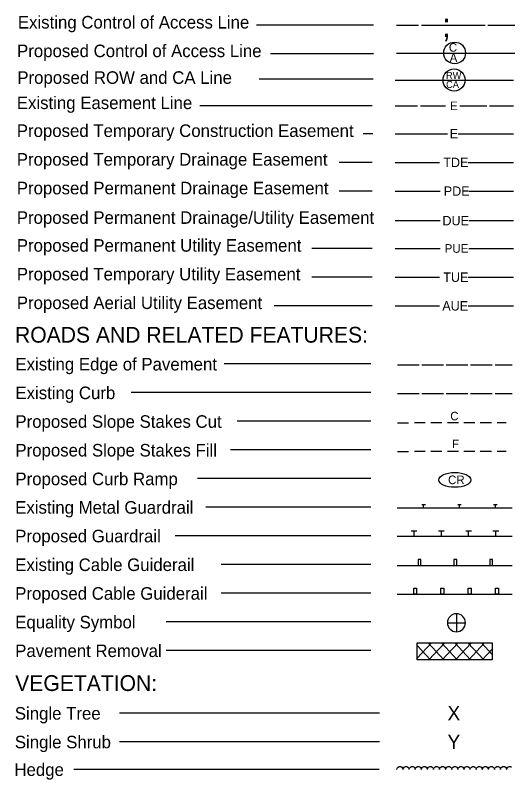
# Model space of a CAD drawing. Extents: x 2058324 to 2059808, y 675202 to 676238.
# Drawn here: x 2058730 to 2059078, y 675202 to 675735 of the extents above; entities that cross this region are included whole.
import ezdxf

# ---------------------------------------------------------------- set-up
doc = ezdxf.new("R2010")
doc.units = 0
for name, color, linetype in [('Prop Easement Permanent Drainage Utility', 7, 'Continuous'), ('Prop WCC CELL', 7, 'Continuous'), ('Sheet Symbology CELL', 7, 'Continuous')]:
    doc.layers.add(name, color=color, linetype=linetype)

msp = doc.modelspace()

# ---------------------------------------------------------------- linework, layer by layer
at = {"layer": 'Prop Easement Permanent Drainage Utility'}
for p, q in [((2058994.73, 675591.85), (2059026.03, 675591.85)), ((2059046.03, 675591.85), (2059077.23, 675591.85))]:
    msp.add_line(p, q, dxfattribs=at)
at = {"layer": 'Prop WCC CELL'}
msp.add_ellipse((2059036.23, 675411.03), major_axis=(11.21, 0), ratio=0.462467, dxfattribs=at)
at = {"layer": 'Sheet Symbology CELL'}
for p, q in [((2058979.44, 675728.07), (2058898.12, 675728.07)), ((2058995.47, 675728.07), (2059010.93, 675728.07)), ((2059012.93, 675728.07), (2059057.34, 675728.07)), ((2059059.34, 675728.07), (2059077.97, 675728.07)), ((2058979.44, 675708.26), (2058907.79, 675708.26)), ((2058995.47, 675708.64), (2059077.97, 675708.64)), ((2058979.33, 675690.5), (2058899.97, 675690.5)), ((2058994.74, 675689.73), (2059077.24, 675689.73)), ((2058978.7, 675671.88), (2058858.42, 675671.88)), ((2058994.73, 675671.88), (2059010.24, 675671.88)), ((2059012.24, 675671.88), (2059029.74, 675671.88)), ((2059039.74, 675671.88), (2059058.49, 675671.88)), ((2059060.49, 675671.88), (2059077.23, 675671.88)), ((2058979.08, 675652.43), (2058972.41, 675652.43)), ((2058994.73, 675652.43), (2058997.34, 675652.43)), ((2058997.34, 675652.43), (2059031.09, 675652.43)), ((2059038.59, 675652.43), (2059072.34, 675652.43)), ((2059072.34, 675652.43), (2059077.23, 675652.43)), ((2058978.7, 675632.43), (2058955.55, 675632.43)), ((2058994.73, 675632.43), (2058998.08, 675632.43)), ((2058998.08, 675632.43), (2059025.58, 675632.43)), ((2059045.58, 675632.43), (2059073.08, 675632.43)), ((2059073.08, 675632.43), (2059077.23, 675632.43)), ((2058978.7, 675612.43), (2058955.55, 675612.43)), ((2058994.73, 675612.43), (2058998.53, 675612.43)), ((2058998.53, 675612.43), (2059026.03, 675612.43)), ((2059046.03, 675612.43), (2059073.53, 675612.43)), ((2059073.53, 675612.43), (2059077.23, 675612.43)), ((2058978.7, 675572.42), (2058936.56, 675572.42)), ((2058994.73, 675572.42), (2058998.57, 675572.42)), ((2058998.57, 675572.42), (2059026.07, 675572.42)), ((2059046.07, 675572.42), (2059073.57, 675572.42)), ((2059073.57, 675572.42), (2059077.23, 675572.42)), ((2058978.7, 675552.42), (2058936.56, 675552.42)), ((2058994.73, 675552.42), (2058998.08, 675552.42)), ((2058998.08, 675552.42), (2059025.58, 675552.42)), ((2059045.58, 675552.42), (2059073.08, 675552.42)), ((2059073.08, 675552.42), (2059077.23, 675552.42)), ((2058978.7, 675532.42), (2058910.24, 675532.42)), ((2058994.73, 675532.42), (2058998.08, 675532.42)), ((2058998.08, 675532.42), (2059025.58, 675532.42)), ((2059045.58, 675532.42), (2059073.08, 675532.42)), ((2059073.08, 675532.42), (2059077.23, 675532.42)), ((2058977.74, 675491.89), (2058875.39, 675491.89)), ((2058996.27, 675491.32), (2059011.27, 675491.32)), ((2059013.27, 675491.32), (2059028.27, 675491.32)), ((2059030.27, 675491.32), (2059045.27, 675491.32)), ((2059047.27, 675491.32), (2059062.27, 675491.32)), ((2059064.27, 675491.32), (2059076.27, 675491.32)), ((2058977.74, 675471.89), (2058810.59, 675471.89)), ((2058996.27, 675471.32), (2059011.27, 675471.32)), ((2059013.27, 675471.32), (2059028.27, 675471.32)), ((2059030.27, 675471.32), (2059045.27, 675471.32)), ((2059047.27, 675471.32), (2059062.27, 675471.32)), ((2059064.27, 675471.32), (2059076.27, 675471.32)), ((2058977.74, 675451.89), (2058884.55, 675451.89)), ((2058996.27, 675450.84), (2059003.87, 675450.84)), ((2059015.57, 675450.84), (2059008.02, 675450.84)), ((2059027.07, 675450.84), (2059019.47, 675450.84)), ((2059038.82, 675450.84), (2059031.02, 675450.84)), ((2059050.27, 675450.84), (2059042.52, 675450.84)), ((2059061.82, 675450.84), (2059053.97, 675450.84)), ((2059072.12, 675450.84), (2059065.72, 675450.84)), ((2058977.74, 675431.89), (2058880, 675431.89)), ((2058996.27, 675430.84), (2059003.87, 675430.84)), ((2059015.57, 675430.84), (2059008.02, 675430.84)), ((2059027.07, 675430.84), (2059019.47, 675430.84)), ((2059038.82, 675430.84), (2059031.02, 675430.84)), ((2059050.27, 675430.84), (2059042.52, 675430.84)), ((2059061.82, 675430.84), (2059053.97, 675430.84)), ((2059072.12, 675430.84), (2059065.72, 675430.84)), ((2058977.74, 675411.89), (2058856.81, 675411.89)), ((2059013.25, 675393.94), (2059015.75, 675393.94)), ((2059014.5, 675391.44), (2059014.5, 675393.94)), ((2059038.25, 675393.94), (2059040.75, 675393.94)), ((2059039.5, 675391.44), (2059039.5, 675393.94)), ((2059063.25, 675393.94), (2059065.75, 675393.94)), ((2059064.5, 675391.44), (2059064.5, 675393.94)), ((2058977.58, 675392.01), (2058862.74, 675392.01)), ((2058996.11, 675391.44), (2059076.11, 675391.44)), ((2058977.58, 675372.01), (2058841.34, 675372.01)), ((2059076.11, 675371.44), (2058996.11, 675371.44)), ((2059005.84, 675375.39), (2059009.84, 675375.39)), ((2059007.84, 675371.44), (2059007.84, 675375.39)), ((2059024.84, 675375.39), (2059028.84, 675375.39)), ((2059026.84, 675371.44), (2059026.84, 675375.39)), ((2059043.84, 675375.39), (2059047.84, 675375.39)), ((2059045.84, 675371.44), (2059045.84, 675375.39)), ((2059062.84, 675375.39), (2059066.84, 675375.39)), ((2059064.84, 675371.44), (2059064.84, 675375.39)), ((2058977.58, 675352.01), (2058873.28, 675352.01)), ((2058996.11, 675351.44), (2059076.11, 675351.44)), ((2058977.58, 675332.01), (2058873.28, 675332.01)), ((2058996.11, 675331.44), (2059076.11, 675331.44)), ((2059037.34, 675317.68), (2059037.34, 675311.43)), ((2058977.58, 675312.01), (2058834.96, 675312.01)), ((2059031.09, 675311.43), (2059037.34, 675311.43)), ((2059037.34, 675311.43), (2059037.34, 675305.18)), ((2059037.34, 675311.43), (2059043.59, 675311.43)), ((2059010.06, 675297.3), (2059062.16, 675297.3)), ((2059010.06, 675285.6), (2059010.06, 675297.3)), ((2059010.06, 675296.7), (2059010.61, 675297.3)), ((2059010.06, 675286.75), (2059019.91, 675297.3)), ((2059028.61, 675285.6), (2059017.61, 675297.3)), ((2059018.21, 675285.6), (2059029.21, 675297.3)), ((2059037.86, 675285.6), (2059026.91, 675297.3)), ((2059027.46, 675285.6), (2059038.51, 675297.3)), ((2059047.16, 675285.6), (2059036.16, 675297.3)), ((2059036.76, 675285.6), (2059047.76, 675297.3)), ((2059056.46, 675285.6), (2059045.41, 675297.3)), ((2059046.06, 675285.6), (2059057.01, 675297.3)), ((2059062.16, 675289.35), (2059054.71, 675297.3)), ((2059062.16, 675297.3), (2059062.16, 675285.6)), ((2058977.58, 675292.01), (2058834.96, 675292.01)), ((2059019.31, 675285.6), (2059010.06, 675295.5)), ((2059055.31, 675285.6), (2059062.16, 675292.9)), ((2059062.16, 675285.6), (2059010.06, 675285.6)), ((2058983.72, 675248.37), (2058802.59, 675248.37)), ((2058983.72, 675228.37), (2058802.59, 675228.37)), ((2058983.45, 675209.11), (2058770.76, 675209.11)), ((2058995.84, 675209.11), (2058996.14, 675210.06)), ((2058996.14, 675210.06), (2058996.74, 675210.71)), ((2058996.74, 675210.71), (2058997.54, 675211.16)), ((2058997.54, 675211.16), (2058998.49, 675211.16)), ((2058998.49, 675211.16), (2058999.29, 675210.66)), ((2058999.29, 675210.66), (2058999.84, 675210.01)), ((2058999.84, 675210.01), (2059000.04, 675209.16)), ((2059000.09, 675209.11), (2059000.39, 675210.06)), ((2059000.39, 675210.06), (2059000.99, 675210.71)), ((2059000.99, 675210.71), (2059001.79, 675211.16)), ((2059001.79, 675211.16), (2059002.74, 675211.16)), ((2059002.74, 675211.16), (2059003.54, 675210.66)), ((2059003.54, 675210.66), (2059004.09, 675210.01)), ((2059004.09, 675210.01), (2059004.29, 675209.16)), ((2059004.34, 675209.11), (2059004.64, 675210.06)), ((2059004.64, 675210.06), (2059005.24, 675210.71)), ((2059005.24, 675210.71), (2059006.04, 675211.16)), ((2059006.04, 675211.16), (2059006.99, 675211.16)), ((2059006.99, 675211.16), (2059007.79, 675210.66)), ((2059007.79, 675210.66), (2059008.34, 675210.01)), ((2059008.34, 675210.01), (2059008.54, 675209.16)), ((2059008.59, 675209.11), (2059008.89, 675210.06)), ((2059008.89, 675210.06), (2059009.49, 675210.71)), ((2059009.49, 675210.71), (2059010.29, 675211.16)), ((2059010.29, 675211.16), (2059011.24, 675211.16)), ((2059011.24, 675211.16), (2059012.04, 675210.66)), ((2059012.04, 675210.66), (2059012.59, 675210.01)), ((2059012.59, 675210.01), (2059012.79, 675209.16)), ((2059012.84, 675209.11), (2059013.14, 675210.06)), ((2059013.14, 675210.06), (2059013.74, 675210.71)), ((2059013.74, 675210.71), (2059014.54, 675211.16)), ((2059014.54, 675211.16), (2059015.49, 675211.16)), ((2059015.49, 675211.16), (2059016.29, 675210.66)), ((2059016.29, 675210.66), (2059016.84, 675210.01)), ((2059016.84, 675210.01), (2059017.04, 675209.16)), ((2059017.09, 675209.11), (2059017.39, 675210.06)), ((2059017.39, 675210.06), (2059017.99, 675210.71)), ((2059017.99, 675210.71), (2059018.79, 675211.16)), ((2059018.79, 675211.16), (2059019.74, 675211.16)), ((2059019.74, 675211.16), (2059020.54, 675210.66)), ((2059020.54, 675210.66), (2059021.09, 675210.01)), ((2059021.09, 675210.01), (2059021.29, 675209.16)), ((2059021.34, 675209.11), (2059021.64, 675210.06)), ((2059021.64, 675210.06), (2059022.24, 675210.71)), ((2059022.24, 675210.71), (2059023.04, 675211.16)), ((2059023.04, 675211.16), (2059023.99, 675211.16)), ((2059023.99, 675211.16), (2059024.79, 675210.66)), ((2059024.79, 675210.66), (2059025.34, 675210.01)), ((2059025.34, 675210.01), (2059025.54, 675209.16)), ((2059025.59, 675209.11), (2059025.89, 675210.06)), ((2059025.89, 675210.06), (2059026.49, 675210.71)), ((2059026.49, 675210.71), (2059027.29, 675211.16)), ((2059027.29, 675211.16), (2059028.24, 675211.16)), ((2059028.24, 675211.16), (2059029.04, 675210.66)), ((2059029.04, 675210.66), (2059029.59, 675210.01)), ((2059029.59, 675210.01), (2059029.79, 675209.16)), ((2059029.84, 675209.11), (2059030.14, 675210.06)), ((2059030.14, 675210.06), (2059030.74, 675210.71)), ((2059030.74, 675210.71), (2059031.54, 675211.16)), ((2059031.54, 675211.16), (2059032.49, 675211.16)), ((2059032.49, 675211.16), (2059033.29, 675210.66)), ((2059033.29, 675210.66), (2059033.84, 675210.01)), ((2059033.84, 675210.01), (2059034.04, 675209.16)), ((2059034.09, 675209.11), (2059034.39, 675210.06)), ((2059034.39, 675210.06), (2059034.99, 675210.71)), ((2059034.99, 675210.71), (2059035.79, 675211.16)), ((2059035.79, 675211.16), (2059036.74, 675211.16)), ((2059036.74, 675211.16), (2059037.54, 675210.66)), ((2059037.54, 675210.66), (2059038.09, 675210.01)), ((2059038.09, 675210.01), (2059038.29, 675209.16)), ((2059038.34, 675209.11), (2059038.64, 675210.06)), ((2059038.64, 675210.06), (2059039.24, 675210.71)), ((2059039.24, 675210.71), (2059040.04, 675211.16)), ((2059040.04, 675211.16), (2059040.99, 675211.16)), ((2059040.99, 675211.16), (2059041.79, 675210.66)), ((2059041.79, 675210.66), (2059042.34, 675210.01)), ((2059042.34, 675210.01), (2059042.54, 675209.16)), ((2059042.59, 675209.11), (2059042.89, 675210.06)), ((2059042.89, 675210.06), (2059043.49, 675210.71)), ((2059043.49, 675210.71), (2059044.29, 675211.16)), ((2059044.29, 675211.16), (2059045.24, 675211.16)), ((2059045.24, 675211.16), (2059046.04, 675210.66)), ((2059046.04, 675210.66), (2059046.59, 675210.01)), ((2059046.59, 675210.01), (2059046.79, 675209.16)), ((2059046.84, 675209.11), (2059047.14, 675210.06)), ((2059047.14, 675210.06), (2059047.74, 675210.71)), ((2059047.74, 675210.71), (2059048.54, 675211.16)), ((2059048.54, 675211.16), (2059049.49, 675211.16)), ((2059049.49, 675211.16), (2059050.29, 675210.66)), ((2059050.29, 675210.66), (2059050.84, 675210.01)), ((2059050.84, 675210.01), (2059051.04, 675209.16)), ((2059051.09, 675209.11), (2059051.39, 675210.06)), ((2059051.39, 675210.06), (2059051.99, 675210.71)), ((2059051.99, 675210.71), (2059052.79, 675211.16)), ((2059052.79, 675211.16), (2059053.74, 675211.16)), ((2059053.74, 675211.16), (2059054.54, 675210.66)), ((2059054.54, 675210.66), (2059055.09, 675210.01)), ((2059055.09, 675210.01), (2059055.29, 675209.16)), ((2059055.34, 675209.11), (2059055.64, 675210.06)), ((2059055.64, 675210.06), (2059056.24, 675210.71)), ((2059056.24, 675210.71), (2059057.04, 675211.16)), ((2059057.04, 675211.16), (2059057.99, 675211.16)), ((2059057.99, 675211.16), (2059058.79, 675210.66)), ((2059058.79, 675210.66), (2059059.34, 675210.01)), ((2059059.34, 675210.01), (2059059.54, 675209.16)), ((2059059.59, 675209.11), (2059059.89, 675210.06)), ((2059059.89, 675210.06), (2059060.49, 675210.71)), ((2059060.49, 675210.71), (2059061.29, 675211.16)), ((2059061.29, 675211.16), (2059062.24, 675211.16)), ((2059062.24, 675211.16), (2059063.04, 675210.66)), ((2059063.04, 675210.66), (2059063.59, 675210.01)), ((2059063.59, 675210.01), (2059063.79, 675209.16)), ((2059063.84, 675209.11), (2059064.14, 675210.06)), ((2059064.14, 675210.06), (2059064.74, 675210.71)), ((2059064.74, 675210.71), (2059065.54, 675211.16)), ((2059065.54, 675211.16), (2059066.49, 675211.16)), ((2059066.49, 675211.16), (2059067.29, 675210.66)), ((2059067.29, 675210.66), (2059067.84, 675210.01)), ((2059067.84, 675210.01), (2059068.04, 675209.16)), ((2059068.09, 675209.11), (2059068.39, 675210.06)), ((2059068.39, 675210.06), (2059068.99, 675210.71)), ((2059068.99, 675210.71), (2059069.79, 675211.16)), ((2059069.79, 675211.16), (2059070.74, 675211.16)), ((2059070.74, 675211.16), (2059071.54, 675210.66)), ((2059071.54, 675210.66), (2059072.09, 675210.01)), ((2059072.09, 675210.01), (2059072.29, 675209.16)), ((2059072.34, 675209.11), (2059072.64, 675210.06)), ((2059072.64, 675210.06), (2059073.24, 675210.71)), ((2059073.24, 675210.71), (2059074.04, 675211.16)), ((2059074.04, 675211.16), (2059074.99, 675211.16)), ((2059074.99, 675211.16), (2059075.79, 675210.66)), ((2059075.79, 675210.66), (2059075.84, 675210.61))]:
    msp.add_line(p, q, dxfattribs=at)
for points in [[(2059010.59, 675351.44), (2059012.59, 675351.44), (2059012.59, 675355.44), (2059010.59, 675355.44)], [(2059035.59, 675351.44), (2059037.59, 675351.44), (2059037.59, 675355.44), (2059035.59, 675355.44)], [(2059060.59, 675351.44), (2059062.59, 675351.44), (2059062.59, 675355.44), (2059060.59, 675355.44)], [(2059007.57, 675335.44), (2059009.57, 675335.44), (2059009.57, 675331.44), (2059007.57, 675331.44)], [(2059026.57, 675335.44), (2059028.57, 675335.44), (2059028.57, 675331.44), (2059026.57, 675331.44)], [(2059045.57, 675335.44), (2059047.57, 675335.44), (2059047.57, 675331.44), (2059045.57, 675331.44)], [(2059064.57, 675335.44), (2059066.57, 675335.44), (2059066.57, 675331.44), (2059064.57, 675331.44)]]:
    msp.add_lwpolyline(points, close=True, dxfattribs=at)
for centre, radius in [((2059036.11, 675708.74), 7.58), ((2059035.73, 675689.88), 7.72)]:
    msp.add_circle(centre, radius, dxfattribs=at)
for start, end in [(89.9944, 179.9989), (359.9944, 89.9989), (179.9944, 269.9989), (269.9944, 359.9989)]:
    msp.add_arc((2059037.34, 675311.42), 6.25, start, end, dxfattribs=at)

# ---------------------------------------------------------------- texts
at = {"layer": 'Prop Easement Permanent Drainage Utility'}
msp.add_text('DUE', height=6.55, rotation=360, dxfattribs=at).set_placement((2059027.62, 675588.55))
at = {"layer": 'Prop WCC CELL'}
msp.add_text('CR', height=6, rotation=360, dxfattribs=at).set_placement((2059031.52, 675408.07))
at = {"layer": 'Sheet Symbology CELL'}
for s, height, p in [('Existing Control of Access Line', 8.75, (2058731.69, 675725.81)), (';', 16.5, (2059027.26, 675719.89)), ('Proposed Control of Access Line', 8.75, (2058731.14, 675705.83)), ('C', 5.94, (2059032.08, 675709.64)), ('A', 5.94, (2059032.68, 675702.5)), ('Proposed ROW and CA Line', 8.75, (2058731.31, 675687.22)), ('RW', 4.838, (2059030.06, 675690.65)), ('CA', 4.838, (2059030.12, 675684.36)), ('Existing Easement Line', 8.75, (2058730.95, 675669.62)), ('E', 6, (2059032.94, 675668.88)), ('Proposed Temporary Construction Easement', 8.75, (2058730.95, 675650.17)), ('E', 6.55, (2059032.69, 675649.13)), ('Proposed Temporary Drainage Easement', 8.75, (2058730.95, 675630.17)), ('TDE', 6.55, (2059028.18, 675629.13)), ('Proposed Permanent Drainage Easement', 8.75, (2058730.95, 675610.17)), ('PDE', 6.55, (2059028.53, 675609.13)), ('Proposed Permanent Drainage/Utility Easement', 8.75, (2058730.95, 675589.59)), ('Proposed Permanent Utility Easement', 8.75, (2058730.95, 675570.16)), ('PUE', 6, (2059029.17, 675569.42)), ('Proposed Temporary Utility Easement', 8.75, (2058730.95, 675550.16)), ('TUE', 6.55, (2059028.16, 675549.12)), ('Proposed Aerial Utility Easement', 8.75, (2058730.95, 675530.16)), ('AUE', 6.55, (2059027.51, 675529.12)), ('ROADS AND RELATED FEATURES:', 11, (2058729.69, 675506.74)), ('Existing Edge of Pavement', 8.75, (2058729.99, 675487.34)), ('Existing Curb', 8.75, (2058729.99, 675467.34)), ('C', 5.93, (2059033.07, 675452.58)), ('Proposed Slope Stakes Cut', 8.75, (2058729.99, 675447.34)), ('Proposed Slope Stakes Fill', 8.75, (2058729.99, 675427.34)), ('F', 5.93, (2059034.27, 675433.21)), ('Proposed Curb Ramp', 8.75, (2058729.99, 675407.34)), ('Existing Metal Guardrail', 8.75, (2058729.83, 675387.46)), ('Proposed Guardrail', 8.75, (2058729.84, 675367.48)), ('Existing Cable Guiderail', 8.75, (2058729.84, 675347.48)), ('Proposed Cable Guiderail', 8.75, (2058729.84, 675327.48)), ('Equality Symbol', 8.75, (2058729.84, 675307.48)), ('Pavement Removal', 8.75, (2058729.84, 675287.48)), ('VEGETATION:', 11, (2058729.83, 675263.82)), ('Single Tree', 8.75, (2058729.56, 675243.84)), ('X', 10, (2059031.11, 675243.37)), ('Single Shrub', 8.75, (2058729.56, 675223.84)), ('Y', 10, (2059031.11, 675223.37)), ('Hedge', 8.75, (2058729.29, 675204.59))]:
    msp.add_text(s, height=height, rotation=360, dxfattribs=at).set_placement(p)

doc.saveas('drawing.dxf')
